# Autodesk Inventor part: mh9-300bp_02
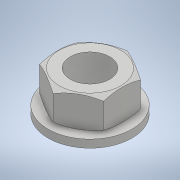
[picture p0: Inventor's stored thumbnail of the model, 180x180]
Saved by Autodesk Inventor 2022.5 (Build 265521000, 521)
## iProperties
Part Number: mh9-300bp_02
Material: 一般
Document SubType Name: Modeling
Designer: ImaoCorp
Density: 1 g/cm^3
Appearance: 既定
Author: ImaoCorp
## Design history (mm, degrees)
feature "mh9-300bp_02"
node "ソリッド1"
